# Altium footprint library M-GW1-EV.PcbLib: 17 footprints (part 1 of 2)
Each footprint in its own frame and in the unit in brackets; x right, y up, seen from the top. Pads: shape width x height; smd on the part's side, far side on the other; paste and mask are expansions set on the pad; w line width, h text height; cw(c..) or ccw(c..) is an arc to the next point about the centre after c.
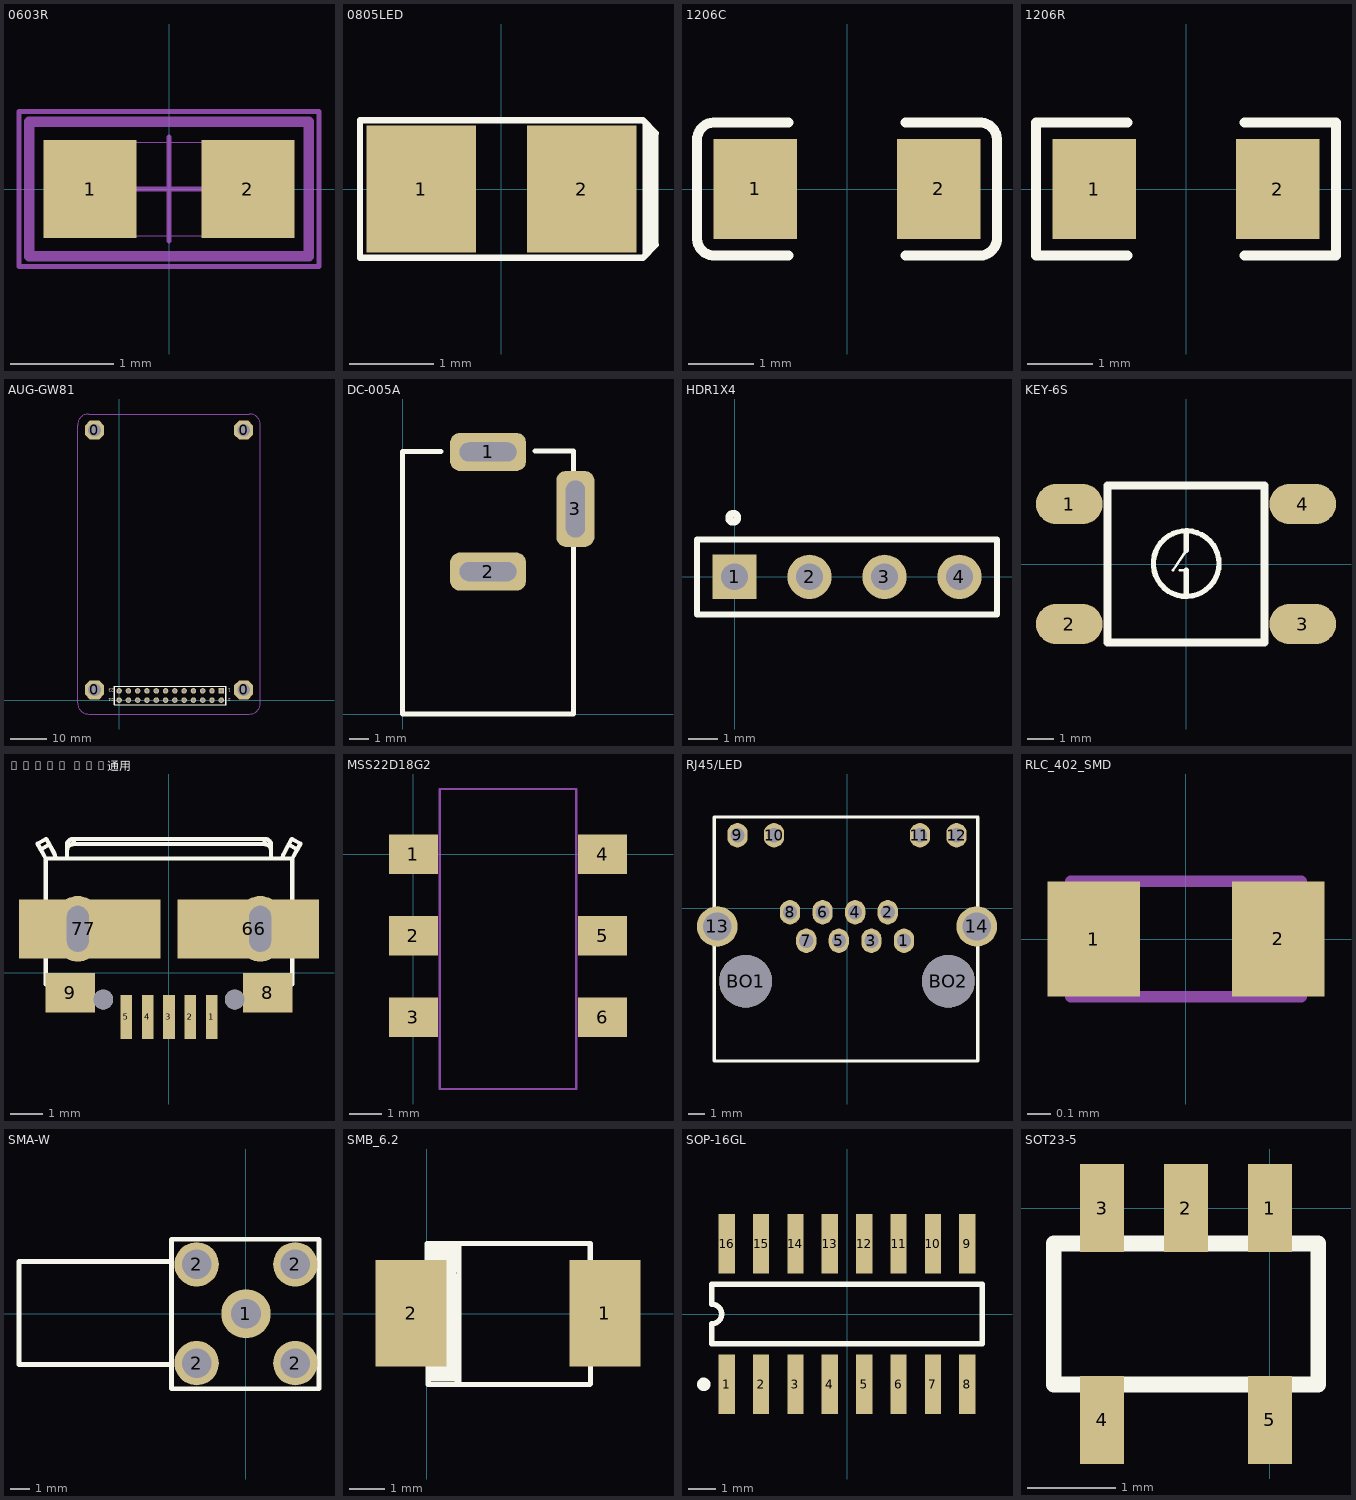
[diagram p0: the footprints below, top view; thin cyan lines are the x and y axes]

## 0603R [mm] "Chip SMD component 402; Body 1.0 x 0.5 mm (LxW typ)"
height 1.75
pads (2):
  rect 0.9x0.95 smd: 1(-0.762,0) 2(0.762,0)
Mechanical 15:
  lines w0.1: -1.35,-0.65 -1.35,0.65 1.35,0.65 1.35,-0.65 -1.35,-0.65
  text "1" at -0.126,-0.345 h0.58
Mechanical 16:
  lines w0.001: -0.85,-0.45 -0.85,0.45 0.85,0.45 0.85,-0.45 -0.85,-0.45
  lines w0.05: -0.5,0 0.5,0 ; 0,-0.5 0,0.5 ; -1.45,-0.75 -1.45,0.75 1.45,0.75 1.45,-0.75 -1.45,-0.75
3D body: height 0.3, standoff 0, extent -0.8,-0.4 0.8,0.4

## 0805LED [mm]
height 1.75
pads (2):
  rect 1.3x1.5 smd: 1(-0.95,0) 2(0.95,0)
Top Overlay:
  region: 1.676,-0.813 1.854,-0.635 1.854,0.635 1.676,0.813
  lines w0.076: 1.829,-0.66 1.676,-0.813 -1.676,-0.813 -1.676,0.813 -1.6,0.813 1.676,0.813 1.829,0.66
3D body: height 0.7, standoff 0, extent -1,-0.625 1,0.625

## 1206C [mil]
height 68.9
pads (2):
  rect 50x60 smd: 1(-55,0) 2(55,0)
Top Overlay:
  lines w6: -90,29 cw(c-79.5,29.5) -80,40 -35,40 ; -90,30 -90,-30 ccw(c-79.5,-29.5) -79,-40 ; -80,-40 -35,-40 ; 35,-40 79,-40 ; 35,40 80,40 ; 79,40 cw(c79.5,29.5) 90,30 90,-29 cw(c79.5,-29.5) 80,-40
3D body: height 39.37, standoff 0, extent -58,-31 67.98,31.99

## 1206R [mil]
height 68.9
pads (2):
  rect 50x60 smd: 1(-55,0) 2(55,0)
Top Overlay:
  lines w6: -35,-40 -90,-40 -90,40 -35,40 ; 35,-40 90,-40 90,40 35,40
3D body: height 23.62, standoff 0, extent -62.93,-31.5 63.06,31.5

## AUG-GW81 [mm] "Connector; Header; 12x2 Position"
height 1.75
pads (28):
  oct 5.2x5.2 hole 3.5: 0(-6.739,2.819) 0(-6.739,73.819) 0(34.061,2.819) 0(34.061,73.819)
  rect 1.5x1.5 hole 0.9: 1(27.94,2.54)
  round 1.5 hole 0.9: 2(27.94,0) 3(25.4,2.54) 4(25.4,0) 5(22.86,2.54) 6(22.86,0) 7(20.32,2.54) 8(20.32,0) 9(17.78,2.54) 10(17.78,0) 11(15.24,2.54) 12(15.24,0) 13(12.7,2.54) 14(12.7,0) 15(10.16,2.54) 16(10.16,0) 17(7.62,2.54) 18(7.62,0) 19(5.08,2.54) 20(5.08,0) 21(2.54,2.54) 22(2.54,0) 23(0,2.54) 24(0,0)
Top Layer:
  lines w0.305: 5.105,0 5.105,0.163
Top Overlay:
  lines w0.2: -1.245,-1.27 -1.245,3.81 29.235,3.81 29.235,-1.27 -1.245,-1.27
  lines w0.203: -1.27,-1.27 29.21,-1.27 29.21,3.81 -1.27,3.81 -1.27,-1.27
  text "1" at 30.505,3.048 h0.76
  text "2" at 30.505,0.508 h0.76
  text "23" at -1.499,3.048 h0.76
  text "24" at -1.499,0.508 h0.76
Mechanical 3:
  lines w0.254: -11.356,-0.771 -11.356,75.213 cw(c-8.356,75.213) -8.356,78.213 ; -11.336,-0.791 ccw(c-8.336,-0.791) -8.336,-3.791 35.645,-3.791 ccw(c35.645,-0.791) 38.645,-0.791 38.645,75.236 ccw(c35.645,75.236) 35.645,78.236 -8.333,78.236

## DC-005A [mm]
height 10
pads (3):
  rrect50% 4x2 hole 1 slot 3 at 0 deg: 1(4.5,13.8) 2(4.5,7.5)
  rrect50% 2x4 hole 1 slot 3 at 90 deg: 3(9.1,10.8)
Top Overlay:
  lines w0.254: 2.018,13.818 0,13.818 0,0 9,0 9,8.8 ; 6.957,13.843 9,13.843 9,12.8
3D body: height 11.02, standoff -3.48, extent -0.003,0.017 9.503,13.843

## HDR1X4 [mm] "Connector; Header; 4 Position"
pads (4):
  rect 1.5x1.5 hole 0.9: 1(0,0)
  round 1.5 hole 0.9: 2(2.54,0) 3(5.08,0) 4(7.62,0)
Top Overlay:
  circle w0.254: c-0.041,2 r0.141
  lines w0.2: -1.27,-1.27 8.89,-1.27 8.89,1.27 -1.27,1.27 -1.27,-1.27
3D body: height 8.54, standoff -3, extent -1.27,-1.27 8.89,1.27

## KEY-6S [mil]
height 21.65
pads (4):
  oval 100x60 smd: 1(-175,90) 2(-175,-90) 3(175,-90) 4(175,90)
Top Overlay:
  circle w8: c0.27,0.61 r49.21
  lines w4: -19.42,-9.24 0.27,20.29 ; -9.57,-9.24 0.27,-9.24
  lines w8: 0.27,-48.61 0.27,-9.23 ; 0.27,20.29 0.27,49.82
  lines w12: -118.11,-118.11 118.11,-118.11 118.11,118.11 -118.11,118.11 -118.11,-118.11
3D body: height 267.87, standoff 2.13, extent -200.64,-122.05 200.65,122.05

## MICRO USB通用 [mm]
height 3.65
pads (13):
  rect 0.35x1.349 smd: 1(1.3,-1.34) 2(0.65,-1.34) 3(0,-1.34) 4(-0.65,-1.34) 5(-1.3,-1.34)
  rect 4.3x1.8 smd: 6(2.413,1.34) 7(-2.413,1.34)
  oval 1.4x2 hole 0.66 slot 1.4 at 90 deg: 6(2.775,1.34) 7(-2.775,1.34)
  rect 1.5x1.2 smd: 8(3,-0.61) 9(-3,-0.61)
  round 0.6 hole 0.6 unplated: ""(-2,-0.81) ""(2,-0.81)
Top Overlay:
  drawing of 379 lines, arcs and shapes, not listed
3D body: height 2.74, standoff -0.26, extent -4.397,-1.533 4.403,4.067

## MSS22D18G2 [mm]
height 1.2
pads (6):
  rect 1.5x1.2 smd: 1(0,0) 2(0,-2.5) 3(0,-5) 4(5.8,0) 5(5.8,-2.5) 6(5.8,-5)
Mechanical 15:
  lines w0.076: 0.8,-7.2 5,-7.2 5,2 4.9,2 0.8,2 0.8,-7.2

## RJ45/LED [mil]
height 68.9
pads (16):
  oval 50x60 hole 35: 1(140.55,-79.92) 2(100.39,-9.84) 3(60.24,-79.92) 4(20.08,-9.84) 5(-20.08,-79.92) 6(-60.24,-9.84) 7(-100.39,-79.92) 8(-140.55,-9.84) 9(-270.08,179.92) 10(-179.92,179.92) 11(179.92,179.92) 12(270.08,179.92)
  round 100 hole 70: 13(-319.88,-44.88) 14(319.88,-44.88)
  round 130 hole 130: BO1(-250,-179.92) BO2(250,-179.92)
Top Overlay:
  lines w7.99: -327.42,-376.69 -327.42,225.16 ; 322.19,-376.69 322.19,225.08
  lines w8: -327.42,-376.69 322.19,-376.69 ; -327.42,225.16 322,225.16 cw(c322,224.89) 322.19,225.08

## RLC_402_SMD [mm] "Chip SMD component 402; Body 1.0 x 0.5 mm (LxW typ)"
height 5
pads (2):
  rect 0.4x0.5 smd: 1(-0.4,0) 2(0.4,0)
Mechanical 16:
  lines w0.05: -0.5,-0.25 -0.5,0.25 0.5,0.25 0.5,-0.25 -0.5,-0.25

## SMA-W [mil]
height 275.98
pads (5):
  round 100 hole 60: 1(0,0)
  round 90 hole 60: 2(-100,-100) 2(-100,100) 2(100,-100) 2(100,100)
Top Overlay:
  lines w10: -152,-103 -460,-103 -460,106 -151,106 ; -151,-152 148,-152 148,151 -151,151 -151,-152
3D body: height 108.06, standoff -447.24, extent -459.69,-139.8 134.8,135.79

## SMB_6.2 [mm]
height 1.75
pads (2):
  rect 2x3 smd: 1(5.014,0.003) 2(-0.444,0.003)
Top Overlay:
  rectangle: 0.722,1.1 0.823,1.201
  rectangle: -0.066,1.1 0.722,1.227
  rectangle: -0.015,1.151 0.798,1.201
  rectangle: 0.518,-1.186 0.849,1.125
  rectangle: 0.036,1.152 0.849,1.939
  rectangle: 0.036,-1.135 0.849,-1.11
  rectangle: -0.015,-1.923 0.849,-1.135
  lines w0.152: 0.014,1.224 0.014,1.975 4.6,1.975 4.6,1.162 4.586,1.148 ; 0.039,-1.189 0.039,-2.002 4.586,-2.002 4.611,-1.976 4.611,-1.163 ; 0.852,-1.951 0.903,-1.9 0.903,1.935

## SOP-16GL [mm]
height 1.2
pads (16):
  rect 0.6x2.2 smd: 1(-4.445,-2.6) 2(-3.175,-2.6) 3(-1.905,-2.6) 4(-0.635,-2.6) 5(0.635,-2.6) 6(1.905,-2.6) 7(3.175,-2.6) 8(4.445,-2.6) 9(4.445,2.6) 10(3.175,2.6) 11(1.905,2.6) 12(0.635,2.6) 13(-0.635,2.6) 14(-1.905,2.6) 15(-3.175,2.6) 16(-4.445,2.6)
Top Overlay:
  circle w0.25: c-5.295,-2.6 r0.125
  lines w0.2: -5,-1.1 5,-1.1 5,1.1 -5,1.1 -5,0.367 cw(c-5,0) -5,-0.367 -5,-1.1
3D body: height 1.8, standoff -0.03, extent -5.524,-3.136 5.018,3.136

## SOT23-5 [mm]
height 1.75
pads (5):
  rect 0.5x1 smd: 1(0,0) 2(-0.95,0) 3(-1.9,0) 4(-1.9,-2.4) 5(0,-2.4)
Top Overlay:
  lines w0.178: -2.45,-2 0.55,-2 0.55,-0.4 -2.45,-0.4 -2.45,-2
3D body: height 1.09, standoff -0.01, extent -2.399,-2.599 0.5,0.201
